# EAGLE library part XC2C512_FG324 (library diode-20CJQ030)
Xilinx's XC2C512 CoolRunner-II CPLD with 512 Macro Cells Description: The CoolRunner-II 512-macrocell device is designed for both high performance and low power applications. This lends power savings to high-end communication equipment and high speed to battery operated devices. Due to the low power stand-by and dynamic operation, overall system reliability is improved This device consists of thirty two Function Blocks inter-connected by a low power Advanced Interconnect Matrix (AIM). The AIM feeds 40 true and complement inputs to each Function Block. The Function Blocks consist of a 40 by 56 P-term PLA and 16 macrocells which contain numerous configuration bits that allow for combinational or registered modes of operation. Additionally, these registers can be globally reset or preset and configured as a D or T flip-flop or as a D latch. There are also multiple clock signals, both global and local product term types, configured on a per macrocell basis. Output pin configurations include slew rate limit, bus hold, pull-up, open drain and programmable grounds. A Schmitt-trigger input is available on a per input pin basis. In addition to storing macrocell output states, the macrocell registers may be configured as "direct input" registers to store signals directly from input pins. Clocking is available on a global or Function Block basis. Three global clocks are available for all Function Blocks as a synchronous clock source. Macrocell registers can be individually configured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
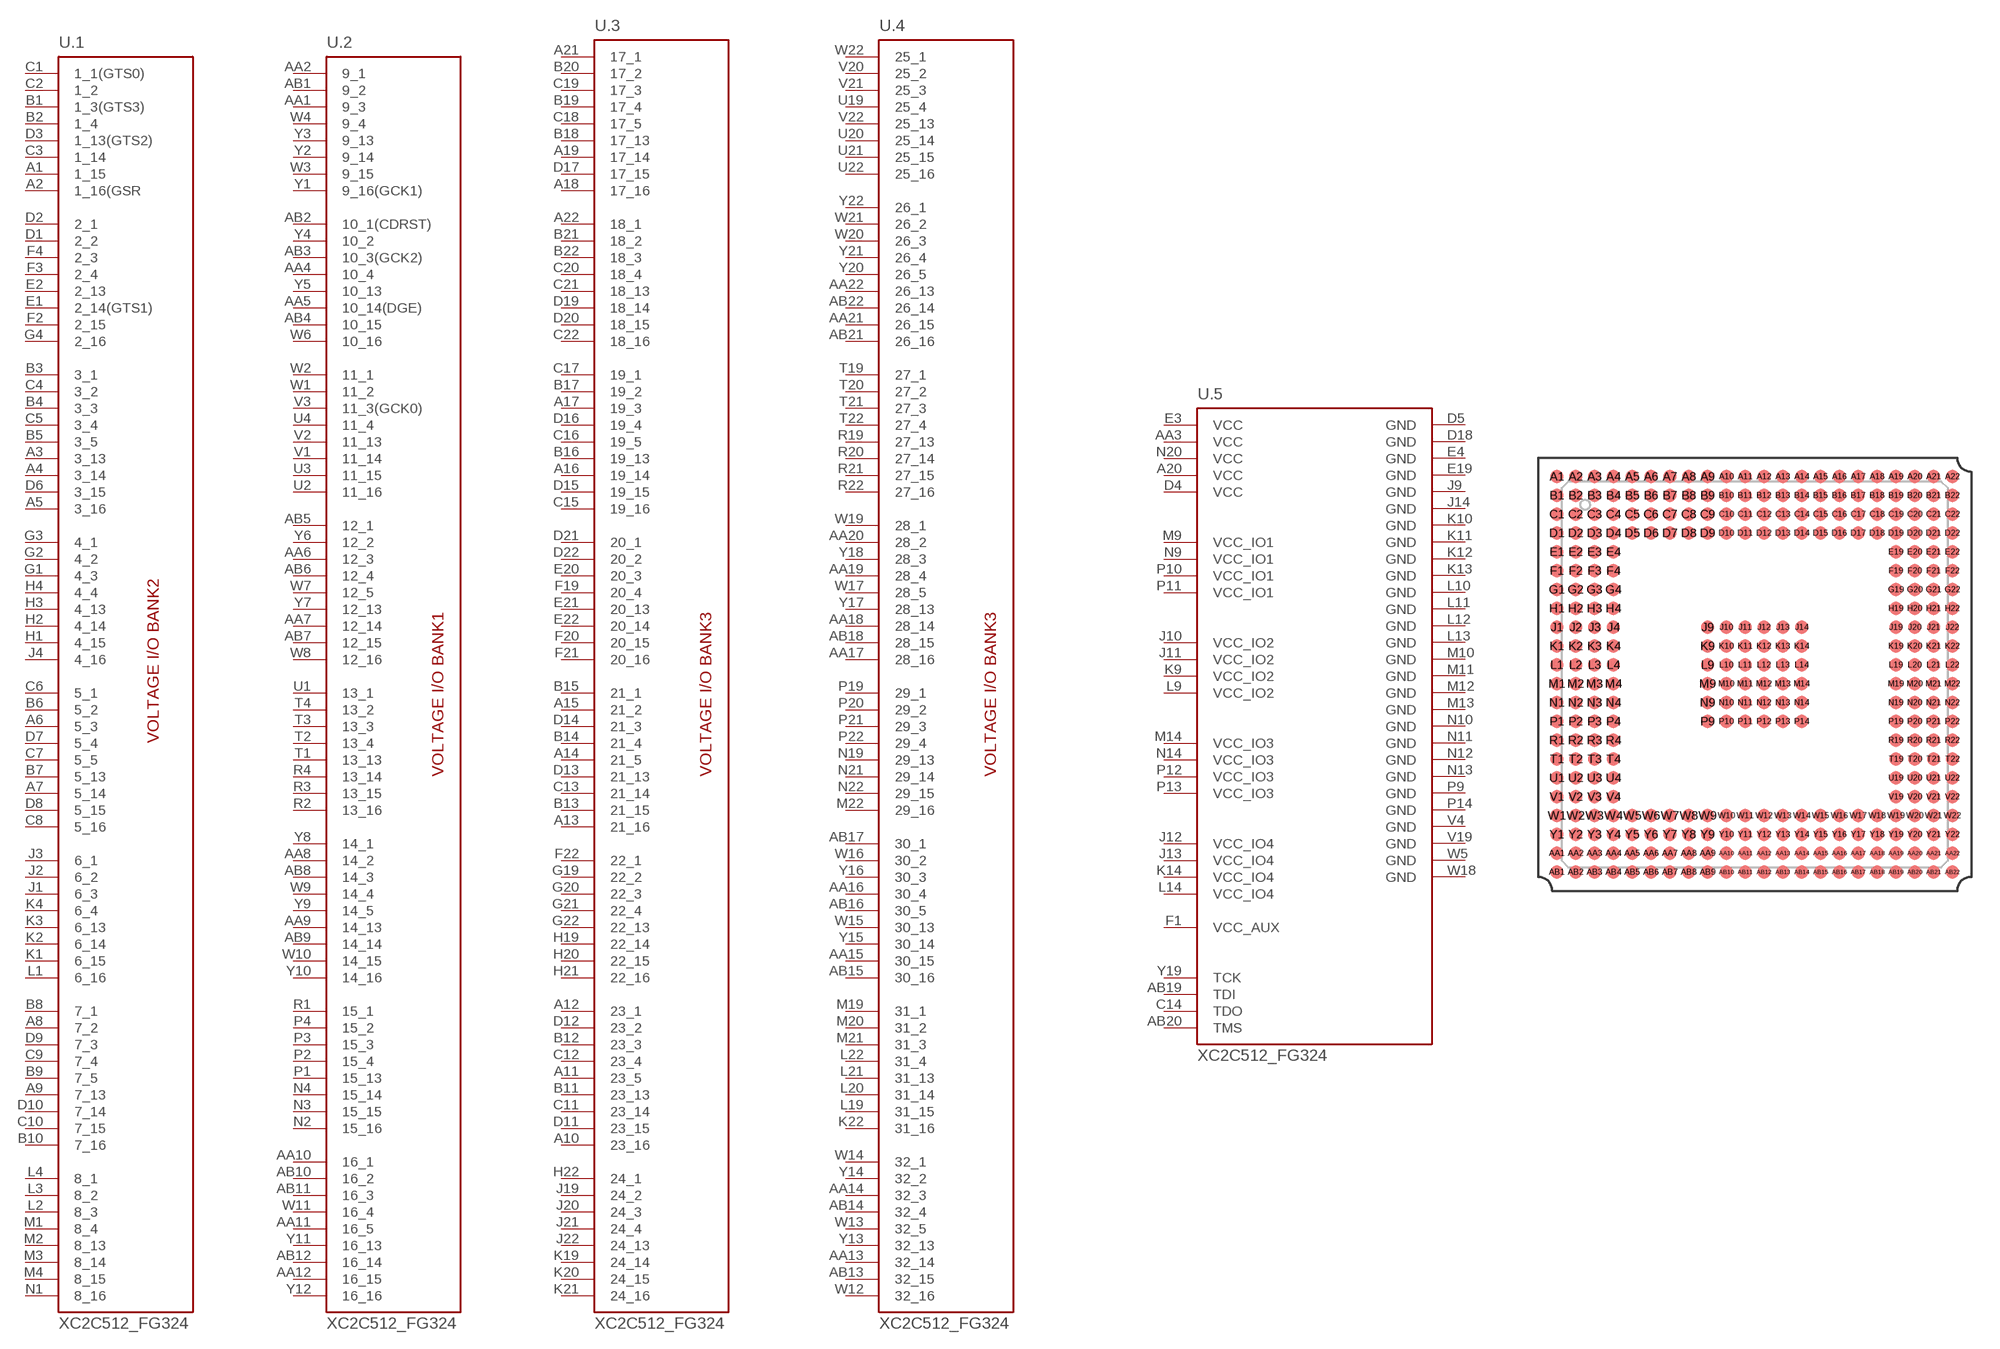
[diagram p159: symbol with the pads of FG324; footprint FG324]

Designator prefix U; gates .1=XC2C512_FG324_1_8 .2=XC2C512_FG324_9_16 .3=XC2C512_FG324_17_24 .4=XC2C512_FG324_25_32 .5=XC2C5120_FG324_PWR

## XC2C512_FG324  [FG324]
A1  .1:1_15
A2  .1:1_16(GSR
A3  .1:3_13
A4  .1:3_14
A5  .1:3_16
A6  .1:5_3
A7  .1:5_14
A8  .1:7_2
A9  .1:7_13
A10  .3:23_16
A11  .3:23_5
A12  .3:23_1
A13  .3:21_16
A14  .3:21_5
A15  .3:21_2
A16  .3:19_14
A17  .3:19_3
A18  .3:17_16
A19  .3:17_14
A20  .5:VCC  pwr
A21  .3:17_1
A22  .3:18_1
AA1  .2:9_3
AA2  .2:9_1
AA3  .5:VCC  pwr
AA4  .2:10_4
AA5  .2:10_14(DGE)
AA6  .2:12_3
AA7  .2:12_14
AA8  .2:14_2
AA9  .2:14_13
AA10  .2:16_1
AA11  .2:16_5
AA12  .2:16_15
AA13  .4:32_14
AA14  .4:32_3
AA15  .4:30_15
AA16  .4:30_4
AA17  .4:28_16
AA18  .4:28_14
AA19  .4:28_4
AA20  .4:28_2
AA21  .4:26_15
AA22  .4:26_13
AB1  .2:9_2
AB2  .2:10_1(CDRST)
AB3  .2:10_3(GCK2)
AB4  .2:10_15
AB5  .2:12_1
AB6  .2:12_4
AB7  .2:12_15
AB8  .2:14_3
AB9  .2:14_14
AB10  .2:16_2
AB11  .2:16_3
AB12  .2:16_14
AB13  .4:32_15
AB14  .4:32_4
AB15  .4:30_16
AB16  .4:30_5
AB17  .4:30_1
AB18  .4:28_15
AB19  .5:TDI  in
AB20  .5:TMS
AB21  .4:26_16
AB22  .4:26_14
B1  .1:1_3(GTS3)
B2  .1:1_4
B3  .1:3_1
B4  .1:3_3
B5  .1:3_5
B6  .1:5_2
B7  .1:5_13
B8  .1:7_1
B9  .1:7_5
B10  .1:7_16
B11  .3:23_13
B12  .3:23_3
B13  .3:21_15
B14  .3:21_4
B15  .3:21_1
B16  .3:19_13
B17  .3:19_2
B18  .3:17_13
B19  .3:17_4
B20  .3:17_2
B21  .3:18_2
B22  .3:18_3
C1  .1:1_1(GTS0)
C2  .1:1_2
C3  .1:1_14
C4  .1:3_2
C5  .1:3_4
C6  .1:5_1
C7  .1:5_5
C8  .1:5_16
C9  .1:7_4
C10  .1:7_15
C11  .3:23_14
C12  .3:23_4
C13  .3:21_14
C14  .5:TDO  out
C15  .3:19_16
C16  .3:19_5
C17  .3:19_1
C18  .3:17_5
C19  .3:17_3
C20  .3:18_4
C21  .3:18_13
C22  .3:18_16
D1  .1:2_2
D2  .1:2_1
D3  .1:1_13(GTS2)
D4  .5:VCC  pwr
D5  .5:GND  pwr
D6  .1:3_15
D7  .1:5_4
D8  .1:5_15
D9  .1:7_3
D10  .1:7_14
D11  .3:23_15
D12  .3:23_2
D13  .3:21_13
D14  .3:21_3
D15  .3:19_15
D16  .3:19_4
D17  .3:17_15
D18  .5:GND  pwr
D19  .3:18_14
D20  .3:18_15
D21  .3:20_1
D22  .3:20_2
E1  .1:2_14(GTS1)
E2  .1:2_13
E3  .5:VCC  pwr
E4  .5:GND  pwr
E19  .5:GND  pwr
E20  .3:20_3
E21  .3:20_13
E22  .3:20_14
F1  .5:VCC_AUX  pwr
F2  .1:2_15
F3  .1:2_4
F4  .1:2_3
F19  .3:20_4
F20  .3:20_15
F21  .3:20_16
F22  .3:22_1
G1  .1:4_3
G2  .1:4_2
G3  .1:4_1
G4  .1:2_16
G19  .3:22_2
G20  .3:22_3
G21  .3:22_4
G22  .3:22_13
H1  .1:4_15
H2  .1:4_14
H3  .1:4_13
H4  .1:4_4
H19  .3:22_14
H20  .3:22_15
H21  .3:22_16
H22  .3:24_1
J1  .1:6_3
J2  .1:6_2
J3  .1:6_1
J4  .1:4_16
J9  .5:GND  pwr
J10  .5:VCC_IO2  pwr
J11  .5:VCC_IO2  pwr
J12  .5:VCC_IO4  pwr
J13  .5:VCC_IO4  pwr
J14  .5:GND  pwr
J19  .3:24_2
J20  .3:24_3
J21  .3:24_4
J22  .3:24_13
K1  .1:6_15
K2  .1:6_14
K3  .1:6_13
K4  .1:6_4
K9  .5:VCC_IO2  pwr
K10  .5:GND  pwr
K11  .5:GND  pwr
K12  .5:GND  pwr
K13  .5:GND  pwr
K14  .5:VCC_IO4  pwr
K19  .3:24_14
K20  .3:24_15
K21  .3:24_16
K22  .4:31_16
L1  .1:6_16
L2  .1:8_3
L3  .1:8_2
L4  .1:8_1
L9  .5:VCC_IO2  pwr
L10  .5:GND  pwr
L11  .5:GND  pwr
L12  .5:GND  pwr
L13  .5:GND  pwr
L14  .5:VCC_IO4  pwr
L19  .4:31_15
L20  .4:31_14
L21  .4:31_13
L22  .4:31_4
M1  .1:8_4
M2  .1:8_13
M3  .1:8_14
M4  .1:8_15
M9  .5:VCC_IO1  pwr
M10  .5:GND  pwr
M11  .5:GND  pwr
M12  .5:GND  pwr
M13  .5:GND  pwr
M14  .5:VCC_IO3  pwr
M19  .4:31_1
M20  .4:31_2
M21  .4:31_3
M22  .4:29_16
N1  .1:8_16
N2  .2:15_16
N3  .2:15_15
N4  .2:15_14
N9  .5:VCC_IO1  pwr
N10  .5:GND  pwr
N11  .5:GND  pwr
N12  .5:GND  pwr
N13  .5:GND  pwr
N14  .5:VCC_IO3  pwr
N19  .4:29_13
N20  .5:VCC  pwr
N21  .4:29_14
N22  .4:29_15
P1  .2:15_13
P2  .2:15_4
P3  .2:15_3
P4  .2:15_2
P9  .5:GND  pwr
P10  .5:VCC_IO1  pwr
P11  .5:VCC_IO1  pwr
P12  .5:VCC_IO3  pwr
P13  .5:VCC_IO3  pwr
P14  .5:GND  pwr
P19  .4:29_1
P20  .4:29_2
P21  .4:29_3
P22  .4:29_4
R1  .2:15_1
R2  .2:13_16
R3  .2:13_15
R4  .2:13_14
R19  .4:27_13
R20  .4:27_14
R21  .4:27_15
R22  .4:27_16
T1  .2:13_13
T2  .2:13_4
T3  .2:13_3
T4  .2:13_2
T19  .4:27_1
T20  .4:27_2
T21  .4:27_3
T22  .4:27_4
U1  .2:13_1
U2  .2:11_16
U3  .2:11_15
U4  .2:11_4
U19  .4:25_4
U20  .4:25_14
U21  .4:25_15
U22  .4:25_16
V1  .2:11_14
V2  .2:11_13
V3  .2:11_3(GCK0)
V4  .5:GND  pwr
V19  .5:GND  pwr
V20  .4:25_2
V21  .4:25_3
V22  .4:25_13
W1  .2:11_2
W2  .2:11_1
W3  .2:9_15
W4  .2:9_4
W5  .5:GND  pwr
W6  .2:10_16
W7  .2:12_5
W8  .2:12_16
W9  .2:14_4
W10  .2:14_15
W11  .2:16_4
W12  .4:32_16
W13  .4:32_5
W14  .4:32_1
W15  .4:30_13
W16  .4:30_2
W17  .4:28_5
W18  .5:GND  pwr
W19  .4:28_1
W20  .4:26_3
W21  .4:26_2
W22  .4:25_1
Y1  .2:9_16(GCK1)
Y2  .2:9_14
Y3  .2:9_13
Y4  .2:10_2
Y5  .2:10_13
Y6  .2:12_2
Y7  .2:12_13
Y8  .2:14_1
Y9  .2:14_5
Y10  .2:14_16
Y11  .2:16_13
Y12  .2:16_16
Y13  .4:32_13
Y14  .4:32_2
Y15  .4:30_14
Y16  .4:30_3
Y17  .4:28_13
Y18  .4:28_3
Y19  .5:TCK  in
Y20  .4:26_5
Y21  .4:26_4
Y22  .4:26_1

## Footprint FG324 (pad centres in mm)
XILINX CPLD Package FG324
smd 0.7 x 0.7: A1 -10.5,10.5; A2 -9.5,10.5; A3 -8.5,10.5; A4 -7.5,10.5; A5 -6.5,10.5; A6 -5.5,10.5; A7 -4.5,10.5; A8 -3.5,10.5; A9 -2.5,10.5; A10 -1.5,10.5; A11 -0.5,10.5; A12 0.5,10.5; A13 1.5,10.5; A14 2.5,10.5; A15 3.5,10.5; A16 4.5,10.5; A17 5.5,10.5; A18 6.5,10.5; A19 7.5,10.5; A20 8.5,10.5; A21 9.5,10.5; A22 10.5,10.5; AA1 -10.5,-9.5; AA2 -9.5,-9.5; AA3 -8.5,-9.5; AA4 -7.5,-9.5; AA5 -6.5,-9.5; AA6 -5.5,-9.5; AA7 -4.5,-9.5; AA8 -3.5,-9.5; AA9 -2.5,-9.5; AA10 -1.5,-9.5; AA11 -0.5,-9.5; AA12 0.5,-9.5; AA13 1.5,-9.5; AA14 2.5,-9.5; AA15 3.5,-9.5; AA16 4.5,-9.5; AA17 5.5,-9.5; AA18 6.5,-9.5; AA19 7.5,-9.5; AA20 8.5,-9.5; AA21 9.5,-9.5; AA22 10.5,-9.5; AB1 -10.5,-10.5; AB2 -9.5,-10.5; AB3 -8.5,-10.5; AB4 -7.5,-10.5; AB5 -6.5,-10.5; AB6 -5.5,-10.5; AB7 -4.5,-10.5; AB8 -3.5,-10.5; AB9 -2.5,-10.5; AB10 -1.5,-10.5; AB11 -0.5,-10.5; AB12 0.5,-10.5; AB13 1.5,-10.5; AB14 2.5,-10.5; AB15 3.5,-10.5; AB16 4.5,-10.5; AB17 5.5,-10.5; AB18 6.5,-10.5; AB19 7.5,-10.5; AB20 8.5,-10.5; AB21 9.5,-10.5; AB22 10.5,-10.5; B1 -10.5,9.5; B2 -9.5,9.5; B3 -8.5,9.5; B4 -7.5,9.5; B5 -6.5,9.5; B6 -5.5,9.5; B7 -4.5,9.5; B8 -3.5,9.5; B9 -2.5,9.5; B10 -1.5,9.5; B11 -0.5,9.5; B12 0.5,9.5; B13 1.5,9.5; B14 2.5,9.5; B15 3.5,9.5; B16 4.5,9.5; B17 5.5,9.5; B18 6.5,9.5; B19 7.5,9.5; B20 8.5,9.5; B21 9.5,9.5; B22 10.5,9.5; C1 -10.5,8.5; C2 -9.5,8.5; C3 -8.5,8.5; C4 -7.5,8.5; C5 -6.5,8.5; C6 -5.5,8.5; C7 -4.5,8.5; C8 -3.5,8.5; C9 -2.5,8.5; C10 -1.5,8.5; C11 -0.5,8.5; C12 0.5,8.5; C13 1.5,8.5; C14 2.5,8.5; C15 3.5,8.5; C16 4.5,8.5; C17 5.5,8.5; C18 6.5,8.5; C19 7.5,8.5; C20 8.5,8.5; C21 9.5,8.5; C22 10.5,8.5; D1 -10.5,7.5; D2 -9.5,7.5; D3 -8.5,7.5; D4 -7.5,7.5; D5 -6.5,7.5; D6 -5.5,7.5; D7 -4.5,7.5; D8 -3.5,7.5; D9 -2.5,7.5; D10 -1.5,7.5; D11 -0.5,7.5; D12 0.5,7.5; D13 1.5,7.5; D14 2.5,7.5; D15 3.5,7.5; D16 4.5,7.5; D17 5.5,7.5; D18 6.5,7.5; D19 7.5,7.5; D20 8.5,7.5; D21 9.5,7.5; D22 10.5,7.5; E1 -10.5,6.5; E2 -9.5,6.5; E3 -8.5,6.5; E4 -7.5,6.5; E19 7.5,6.5; E20 8.5,6.5; E21 9.5,6.5; E22 10.5,6.5; F1 -10.5,5.5; F2 -9.5,5.5; F3 -8.5,5.5; F4 -7.5,5.5; F19 7.5,5.5; F20 8.5,5.5; F21 9.5,5.5; F22 10.5,5.5; G1 -10.5,4.5; G2 -9.5,4.5; G3 -8.5,4.5; G4 -7.5,4.5; G19 7.5,4.5; G20 8.5,4.5; G21 9.5,4.5; G22 10.5,4.5; H1 -10.5,3.5; H2 -9.5,3.5; H3 -8.5,3.5; H4 -7.5,3.5; H19 7.5,3.5; H20 8.5,3.5; H21 9.5,3.5; H22 10.5,3.5; J1 -10.5,2.5; J2 -9.5,2.5; J3 -8.5,2.5; J4 -7.5,2.5; J9 -2.5,2.5; J10 -1.5,2.5; J11 -0.5,2.5; J12 0.5,2.5; J13 1.5,2.5; J14 2.5,2.5; J19 7.5,2.5; J20 8.5,2.5; J21 9.5,2.5; J22 10.5,2.5; K1 -10.5,1.5; K2 -9.5,1.5; K3 -8.5,1.5; K4 -7.5,1.5; K9 -2.5,1.5; K10 -1.5,1.5; K11 -0.5,1.5; K12 0.5,1.5; K13 1.5,1.5; K14 2.5,1.5; K19 7.5,1.5; K20 8.5,1.5; K21 9.5,1.5; K22 10.5,1.5; L1 -10.5,0.5; L2 -9.5,0.5; L3 -8.5,0.5; L4 -7.5,0.5; L9 -2.5,0.5; L10 -1.5,0.5; L11 -0.5,0.5; L12 0.5,0.5; L13 1.5,0.5; L14 2.5,0.5; L19 7.5,0.5; L20 8.5,0.5; L21 9.5,0.5; L22 10.5,0.5; M1 -10.5,-0.5; M2 -9.5,-0.5; M3 -8.5,-0.5; M4 -7.5,-0.5; M9 -2.5,-0.5; M10 -1.5,-0.5; M11 -0.5,-0.5; M12 0.5,-0.5; M13 1.5,-0.5; M14 2.5,-0.5; M19 7.5,-0.5; M20 8.5,-0.5; M21 9.5,-0.5; M22 10.5,-0.5; N1 -10.5,-1.5; N2 -9.5,-1.5; N3 -8.5,-1.5; N4 -7.5,-1.5; N9 -2.5,-1.5; N10 -1.5,-1.5; N11 -0.5,-1.5; N12 0.5,-1.5; N13 1.5,-1.5; N14 2.5,-1.5; N19 7.5,-1.5; N20 8.5,-1.5; N21 9.5,-1.5; N22 10.5,-1.5; P1 -10.5,-2.5; P2 -9.5,-2.5; P3 -8.5,-2.5; P4 -7.5,-2.5; P9 -2.5,-2.5; P10 -1.5,-2.5; P11 -0.5,-2.5; P12 0.5,-2.5; P13 1.5,-2.5; P14 2.5,-2.5; P19 7.5,-2.5; P20 8.5,-2.5; P21 9.5,-2.5; P22 10.5,-2.5; R1 -10.5,-3.5; R2 -9.5,-3.5; R3 -8.5,-3.5; R4 -7.5,-3.5; R19 7.5,-3.5; R20 8.5,-3.5; R21 9.5,-3.5; R22 10.5,-3.5; T1 -10.5,-4.5; T2 -9.5,-4.5; T3 -8.5,-4.5; T4 -7.5,-4.5; T19 7.5,-4.5; T20 8.5,-4.5; T21 9.5,-4.5; T22 10.5,-4.5; U1 -10.5,-5.5; U2 -9.5,-5.5; U3 -8.5,-5.5; U4 -7.5,-5.5; U19 7.5,-5.5; U20 8.5,-5.5; U21 9.5,-5.5; U22 10.5,-5.5; V1 -10.5,-6.5; V2 -9.5,-6.5; V3 -8.5,-6.5; V4 -7.5,-6.5; V19 7.5,-6.5; V20 8.5,-6.5; V21 9.5,-6.5; V22 10.5,-6.5; W1 -10.5,-7.5; W2 -9.5,-7.5; W3 -8.5,-7.5; W4 -7.5,-7.5; W5 -6.5,-7.5; W6 -5.5,-7.5; W7 -4.5,-7.5; W8 -3.5,-7.5; W9 -2.5,-7.5; W10 -1.5,-7.5; W11 -0.5,-7.5; W12 0.5,-7.5; W13 1.5,-7.5; W14 2.5,-7.5; W15 3.5,-7.5; W16 4.5,-7.5; W17 5.5,-7.5; W18 6.5,-7.5; W19 7.5,-7.5; W20 8.5,-7.5; W21 9.5,-7.5; W22 10.5,-7.5; Y1 -10.5,-8.5; Y2 -9.5,-8.5; Y3 -8.5,-8.5; Y4 -7.5,-8.5; Y5 -6.5,-8.5; Y6 -5.5,-8.5; Y7 -4.5,-8.5; Y8 -3.5,-8.5; Y9 -2.5,-8.5; Y10 -1.5,-8.5; Y11 -0.5,-8.5; Y12 0.5,-8.5; Y13 1.5,-8.5; Y14 2.5,-8.5; Y15 3.5,-8.5; Y16 4.5,-8.5; Y17 5.5,-8.5; Y18 6.5,-8.5; Y19 7.5,-8.5; Y20 8.5,-8.5; Y21 9.5,-8.5; Y22 10.5,-8.5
